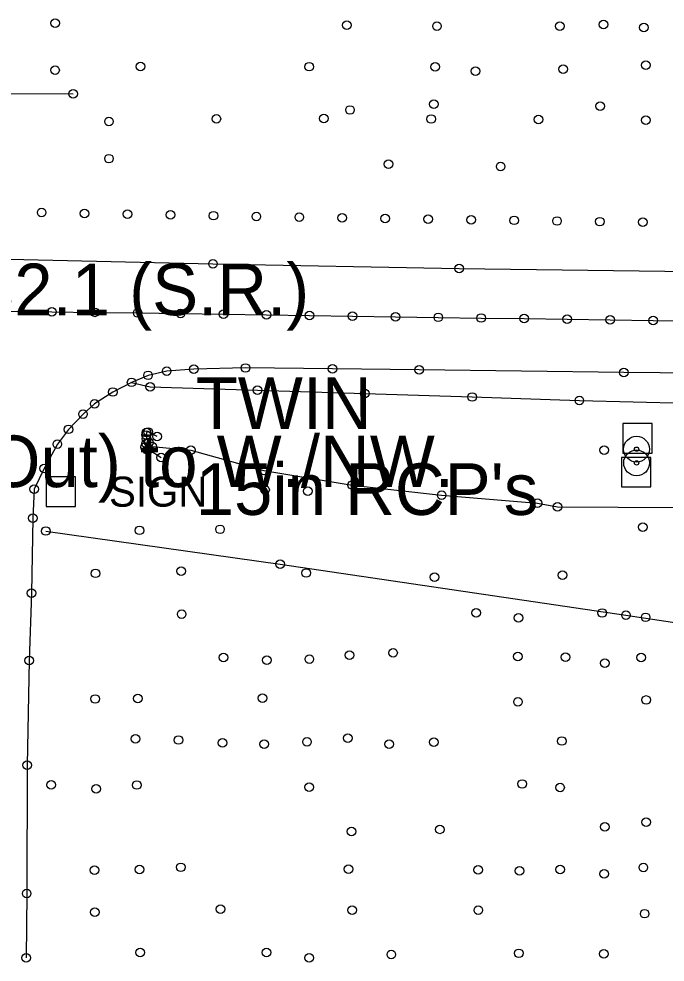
# Model space of a CAD drawing. Extents: x 20503438 to 20508873, y 7964251 to 7984667.
# Drawn here: x 20505557.5 to 20505708, y 7970387.8 to 7970607.3 of the extents above; entities that cross this region are included whole.
import ezdxf

# ---------------------------------------------------------------- set-up
doc = ezdxf.new("R2010")
doc.units = 0
for name, color, linetype in [('SurBreakLine', 7, 'Continuous'), ('SurConcreteSlab', 7, 'Continuous'), ('SurDrainageArrowUp', 7, 'Continuous'), ('SurEdgeShoulderPaved', 7, 'Continuous'), ('SurEdgeShoulderUnpaved', 7, 'Continuous'), ('SurFenceChainLink', 7, 'Continuous'), ('SurPointsNonDTM', 7, 'Continuous'), ('SurRoadPoints', 7, 'Continuous'), ('SurSurveyPoints', 7, 'Continuous'), ('SurTxtDrainage', 7, 'Continuous')]:
    doc.layers.add(name, color=color, linetype=linetype)

msp = doc.modelspace()

# ---------------------------------------------------------------- linework, layer by layer
at = {"layer": 'SurBreakLine'}
for points in [[(20504771.9, 7970563.37), (20504797.86, 7970563), (20504843.99, 7970562.34), (20504867.04, 7970562.01), (20505027.11, 7970559.46), (20505056.57, 7970559.02), (20505122.33, 7970557.99), (20505134.3, 7970557.78), (20505181.34, 7970557.02), (20505190.04, 7970556.88), (20505298.19, 7970555.19), (20505381.79, 7970553.77), (20505481.65, 7970551.95), (20505538.21, 7970551.74), (20505602.69, 7970550.28), (20505659.98, 7970549.19), (20505725.91, 7970548.38)], [(20505589.71, 7970510.09), (20505587.59, 7970511.17), (20505587.24, 7970511.05), (20505587.15, 7970510.47), (20505587.23, 7970509.59), (20505587.78, 7970508.72), (20505587.1, 7970508.47), (20505586.93, 7970507.67), (20505587.47, 7970506.97), (20505587.76, 7970507.09), (20505590.64, 7970505.21)]]:
    msp.add_lwpolyline(points, dxfattribs=at)
at = {"layer": 'SurConcreteSlab'}
for points in [[(20505515.18, 7970539.88), (20505525.17, 7970539.73), (20505535.17, 7970539.59), (20505545.17, 7970539.44), (20505555.17, 7970539.3), (20505565.17, 7970539.15), (20505575.17, 7970539), (20505585.16, 7970538.86), (20505595.16, 7970538.71), (20505605.16, 7970538.57), (20505615.16, 7970538.42), (20505625.16, 7970538.27), (20505635.16, 7970538.13), (20505645.16, 7970537.98), (20505655.15, 7970537.84), (20505665.15, 7970537.69), (20505675.15, 7970537.55), (20505685.15, 7970537.4), (20505695.15, 7970537.25), (20505705.15, 7970537.12), (20505715.14, 7970537)], [(20505559.92, 7970458.02), (20505559.41, 7970433.63), (20505559.32, 7970403.8), (20505559.19, 7970388.82)]]:
    msp.add_lwpolyline(points, dxfattribs=at)
at = {"layer": 'SurDrainageArrowUp'}
for points in [[(20505509.27, 7970583.65), (20505510.79, 7970583.61), (20505512.44, 7970584.29), (20505514.65, 7970584.86), (20505521.9, 7970588.08), (20505529.65, 7970588.65), (20505549.4, 7970589.9), (20505570.14, 7970589.83)], [(20505588.51, 7970507.81), (20505597.53, 7970506.94), (20505614.51, 7970502.19), (20505635.08, 7970498.83), (20505655.93, 7970496.49), (20505678.23, 7970494.58), (20505682.9, 7970493.73), (20505711.11, 7970493.62), (20505731.16, 7970493.62), (20505757.46, 7970492.01), (20505802.13, 7970488.46), (20505848.74, 7970485.55), (20505856.14, 7970483.32), (20505901.79, 7970481.39), (20505945.72, 7970472.48), (20505988.92, 7970467.48), (20505998.29, 7970466.36)]]:
    msp.add_lwpolyline(points, dxfattribs=at)
at = {"layer": 'SurEdgeShoulderPaved'}
msp.add_lwpolyline([(20505723.75, 7970524.74), (20505698.34, 7970525.01), (20505650.69, 7970525.63), (20505630.49, 7970525.84), (20505610.28, 7970526.06), (20505598.23, 7970525.81), (20505591.91, 7970525.33), (20505587.57, 7970524.35), (20505583.75, 7970522.72), (20505579.38, 7970520.47), (20505575.14, 7970517.72), (20505572.43, 7970515.33), (20505569.03, 7970511.78), (20505566.46, 7970508.31), (20505563.37, 7970502.65), (20505561.08, 7970497.86), (20505560.73, 7970491.09), (20505560.42, 7970473.69), (20505559.92, 7970458.02)], dxfattribs=at)
at = {"layer": 'SurEdgeShoulderUnpaved'}
msp.add_lwpolyline([(20505583.75, 7970522.72), (20505588.05, 7970521.67), (20505613.04, 7970520.89), (20505638.02, 7970520.1), (20505663.01, 7970519.31), (20505687.99, 7970518.52), (20505712.98, 7970517.9), (20505737.97, 7970517.38), (20505762.96, 7970516.86), (20505787.95, 7970516.34), (20505812.95, 7970515.82), (20505837.94, 7970515.3), (20505862.93, 7970514.78), (20505887.92, 7970514.26), (20505912.91, 7970514.05), (20505937.9, 7970513.99), (20505962.89, 7970513.93), (20505987.89, 7970513.87), (20506012.76, 7970511.67), (20506037.35, 7970507.53), (20506060.92, 7970500.21), (20506079.1, 7970483.65), (20506094.14, 7970463.86), (20506101.05, 7970448.2)], dxfattribs=at)
at = {"layer": 'SurFenceChainLink'}
msp.add_lwpolyline([(20505563.79, 7970488.13), (20505618.36, 7970480.42), (20505698.84, 7970468.55), (20505760.89, 7970459.22), (20505831.24, 7970448.68), (20505921.66, 7970435.36), (20506003.71, 7970422.97), (20506019.92, 7970394.05)], dxfattribs=at)
at = {"layer": 'SurPointsNonDTM'}
for centre in [(20505563.79, 7970488.13), (20505618.36, 7970480.42), (20505698.84, 7970468.55)]:
    msp.add_circle(centre, 1, dxfattribs=at)
at = {"layer": 'SurRoadPoints'}
for points in [[(20505701.52, 7970506.25), (20505701.52, 7970506.25), (20505704.95, 7970506.25), (20505704.95, 7970513.11), (20505698.09, 7970513.11), (20505698.09, 7970506.25), (20505701.52, 7970506.25)], [(20505701.21, 7970498.4), (20505701.21, 7970498.4), (20505704.64, 7970498.4), (20505704.64, 7970505.26), (20505697.78, 7970505.26), (20505697.78, 7970498.4), (20505701.21, 7970498.4)], [(20505567.28, 7970493.86), (20505567.28, 7970493.86), (20505570.71, 7970493.86), (20505570.71, 7970500.72), (20505563.85, 7970500.72), (20505563.85, 7970493.86), (20505567.28, 7970493.86)]]:
    msp.add_lwpolyline(points, dxfattribs=at)
for centre, radius in [((20505701.3, 7970507.17), 3), ((20505701.3, 7970507.17), 0.5), ((20505701.31, 7970503.97), 3), ((20505701.31, 7970503.97), 0.5)]:
    msp.add_circle(centre, radius, dxfattribs=at)
at = {"layer": 'SurSurveyPoints'}
for centre in [(20505565.94, 7970606.29), (20505633.87, 7970605.85), (20505654.84, 7970605.59), (20505683.44, 7970605.57), (20505693.62, 7970606), (20505703, 7970605.27), (20505703.46, 7970596.52), (20505565.92, 7970595.38), (20505585.82, 7970596.18), (20505625.09, 7970596.16), (20505654.39, 7970596.12), (20505663.81, 7970595.15), (20505684.21, 7970595.58), (20505570.14, 7970589.83), (20505634.59, 7970586.09), (20505654.11, 7970587.46), (20505692.81, 7970586.98), (20505578.48, 7970583.43), (20505603.48, 7970584.03), (20505628.47, 7970584.12), (20505653.47, 7970583.99), (20505678.47, 7970583.86), (20505703.47, 7970583.73), (20505578.48, 7970574.77), (20505643.53, 7970573.47), (20505669.66, 7970572.93), (20505562.8, 7970562.21), (20505572.8, 7970562.03), (20505582.8, 7970561.85), (20505592.8, 7970561.68), (20505602.79, 7970561.5), (20505612.79, 7970561.32), (20505622.79, 7970561.16), (20505632.79, 7970561.01), (20505642.79, 7970560.86), (20505652.79, 7970560.71), (20505662.79, 7970560.56), (20505672.79, 7970560.41), (20505682.79, 7970560.26), (20505692.78, 7970560.11), (20505702.78, 7970559.97), (20505602.69, 7970550.28), (20505659.98, 7970549.19), (20505565.17, 7970539.15), (20505575.17, 7970539), (20505585.16, 7970538.86), (20505595.16, 7970538.71), (20505605.16, 7970538.57), (20505615.16, 7970538.42), (20505625.16, 7970538.27), (20505635.16, 7970538.13), (20505645.16, 7970537.98), (20505655.15, 7970537.84), (20505665.15, 7970537.69), (20505675.15, 7970537.55), (20505685.15, 7970537.4), (20505695.15, 7970537.25), (20505705.15, 7970537.12), (20505587.57, 7970524.35), (20505591.91, 7970525.33), (20505598.23, 7970525.81), (20505610.28, 7970526.06), (20505630.49, 7970525.84), (20505650.69, 7970525.63), (20505698.34, 7970525.01), (20505583.75, 7970522.72), (20505579.38, 7970520.47), (20505588.05, 7970521.67), (20505613.04, 7970520.89), (20505638.02, 7970520.1), (20505575.14, 7970517.72), (20505663.01, 7970519.31), (20505687.99, 7970518.52), (20505572.43, 7970515.33), (20505569.03, 7970511.78), (20505587.24, 7970511.05), (20505587.59, 7970511.17), (20505587.15, 7970510.47), (20505587.23, 7970509.59), (20505587.78, 7970508.72), (20505589.71, 7970510.09), (20505566.46, 7970508.31), (20505586.93, 7970507.67), (20505587.1, 7970508.47), (20505587.47, 7970506.97), (20505587.76, 7970507.09), (20505588.51, 7970507.81), (20505597.53, 7970506.94), (20505693.77, 7970506.96), (20505590.64, 7970505.21), (20505563.37, 7970502.65), (20505614.51, 7970502.19), (20505561.08, 7970497.86), (20505614.81, 7970497.7), (20505635.08, 7970498.83), (20505624.75, 7970497.39), (20505655.93, 7970496.49), (20505678.23, 7970494.58), (20505682.9, 7970493.73), (20505560.73, 7970491.09), (20505702.74, 7970489), (20505585.57, 7970488.28), (20505604.33, 7970488.52), (20505575.36, 7970478.28), (20505595.27, 7970478.81), (20505624.37, 7970478.36), (20505684.09, 7970477.86), (20505654.25, 7970477.39), (20505560.42, 7970473.69), (20505663.94, 7970469.07), (20505693.29, 7970469.06), (20505595.4, 7970468.78), (20505673.83, 7970467.91), (20505703.42, 7970468.05), (20505605.15, 7970458.72), (20505615.24, 7970458.09), (20505625.13, 7970458.33), (20505634.46, 7970459.22), (20505644.61, 7970459.81), (20505673.68, 7970458.92), (20505684.79, 7970458.77), (20505702.36, 7970458.69), (20505559.92, 7970458.02), (20505559.92, 7970458.02), (20505693.92, 7970457.39), (20505575.26, 7970449.05), (20505585.21, 7970449.14), (20505614.22, 7970449.23), (20505673.7, 7970448.4), (20505703.55, 7970448.82), (20505584.67, 7970439.75), (20505594.65, 7970439.5), (20505604.92, 7970438.83), (20505614.61, 7970438.54), (20505624.58, 7970439.08), (20505634.1, 7970439.92), (20505643.68, 7970438.55), (20505654.1, 7970439.01), (20505683.89, 7970439.27), (20505559.41, 7970433.63), (20505565.03, 7970429.07), (20505575.51, 7970428.12), (20505584.97, 7970429.03), (20505625.11, 7970428.55), (20505674.68, 7970429.27), (20505683.49, 7970428.48), (20505655.48, 7970418.71), (20505693.93, 7970419.33), (20505703.52, 7970420.41), (20505634.96, 7970418.22), (20505595.2, 7970409.88), (20505702.89, 7970409.81), (20505575.1, 7970409.23), (20505585.56, 7970409.37), (20505634.22, 7970409.45), (20505664.43, 7970409.27), (20505674.05, 7970409.08), (20505683.53, 7970409.36), (20505693.75, 7970408.39), (20505559.32, 7970403.8), (20505575.16, 7970399.45), (20505604.42, 7970400.12), (20505635.07, 7970399.91), (20505664.46, 7970399.92), (20505703.19, 7970399.09), (20505585.75, 7970390.09), (20505615.17, 7970390.06), (20505559.19, 7970388.82), (20505625.08, 7970388.85), (20505644.21, 7970389.57), (20505673.87, 7970389.87), (20505693.7, 7970389.77)]:
    msp.add_circle(centre, 1, dxfattribs=at)

# ---------------------------------------------------------------- texts
at = {"layer": 'SurRoadPoints'}
msp.add_text('SIGN', height=6.995, rotation=360, dxfattribs=at).set_placement((20505578.49, 7970493.79))
at = {"layer": 'SurTxtDrainage'}
for s, p in [('Sta. 104+32.1 (S.R.)', (20505478.35, 7970538.34)), ('TWIN', (20505598.66, 7970511.87)), ('18" RCP (Out) to W./NW.', (20505478.35, 7970498.34)), ("15in RCP's", (20505598.66, 7970491.87))]:
    msp.add_text(s, height=12, dxfattribs=at).set_placement(p)

doc.saveas('drawing.dxf')
